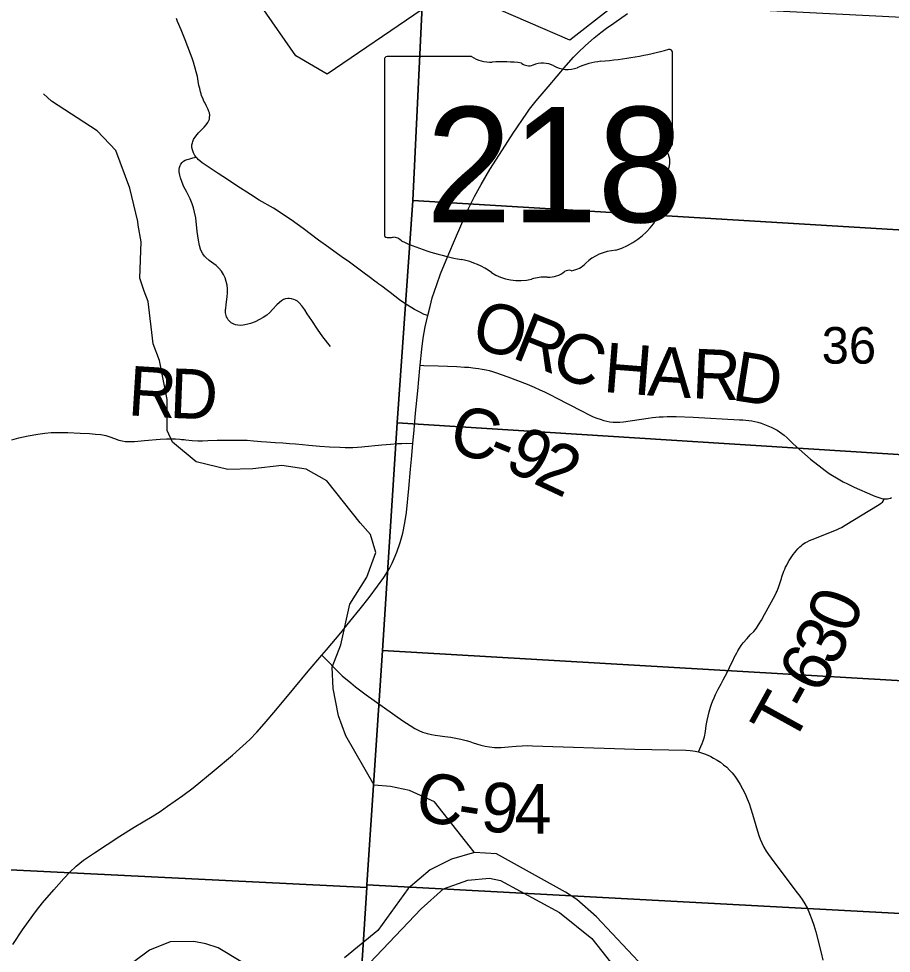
# Model space of a CAD drawing. Extents: x 21.4 to 65.3, y 4 to 26.
# Drawn here: x 25.873 to 26.871, y 19.331 to 20.4 of the extents above; entities that cross this region are included whole.
import ezdxf

# ---------------------------------------------------------------- set-up
doc = ezdxf.new("R2010")
doc.units = 0
for name, color, linetype in [('GM_X_County_Road', 7, 'Continuous'), ('GM_X_County_Road_Text', 7, 'Continuous'), ('GM_X_Major_River', 7, 'Continuous'), ('GM_X_Minor_River', 7, 'Continuous'), ('GM_X_Section', 7, 'Continuous'), ('GM_X_Section_Text', 7, 'Continuous'), ('GM_X_State_Location', 7, 'Continuous'), ('GM_X_State_Route', 7, 'Continuous'), ('GM_X_State_Shield', 7, 'Continuous'), ('GM_X_Township_Road', 7, 'Continuous'), ('GM_X_Township_Road_Text', 7, 'Continuous')]:
    doc.layers.add(name, color=color, linetype=linetype)

msp = doc.modelspace()

# ---------------------------------------------------------------- linework, layer by layer
at = {"layer": 'GM_X_County_Road'}
for points in [[(26.2896, 20.0931), (26.288, 20.0943), (26.2847, 20.0967), (26.2828, 20.0982), (26.28, 20.1003), (26.2751, 20.1041), (26.2662, 20.1106), (26.2586, 20.1162), (26.251, 20.1217), (26.2417, 20.1284), (26.2275, 20.1385), (26.2158, 20.1472), (26.1982, 20.1603), (26.1845, 20.1703), (26.1643, 20.1835), (26.1476, 20.193), (26.138, 20.1992), (26.1221, 20.2094), (26.1117, 20.2163), (26.1007, 20.2234), (26.0893, 20.2309), (26.0825, 20.2356), (26.0781, 20.2392), (26.0767, 20.2407), (26.0756, 20.242), (26.0743, 20.2438), (26.0734, 20.2453), (26.0725, 20.2469), (26.0713, 20.2503), (26.0707, 20.2532), (26.0708, 20.2562), (26.0713, 20.2584), (26.0718, 20.26), (26.0726, 20.2622), (26.0741, 20.2647), (26.0768, 20.268), (26.0785, 20.2697), (26.085, 20.2763), (26.0872, 20.2789), (26.089, 20.2815), (26.0903, 20.2838), (26.0905, 20.2847), (26.0908, 20.2856), (26.0911, 20.2873), (26.0912, 20.2901), (26.0908, 20.2926), (26.0903, 20.2943), (26.0893, 20.2966), (26.0872, 20.3011), (26.0855, 20.3044), (26.0846, 20.306), (26.0835, 20.3082), (26.0817, 20.3127), (26.0812, 20.3145), (26.0806, 20.3168), (26.0797, 20.3204), (26.0788, 20.3239), (26.0778, 20.3288), (26.077, 20.3342), (26.0756, 20.3395), (26.0725, 20.3506), (26.0709, 20.3553), (26.0691, 20.3604), (26.0632, 20.3761), (26.0585, 20.3876), (26.0544, 20.3973), (26.053, 20.4005)], [(26.3407, 20.0607), (26.3366, 20.0622), (26.3315, 20.0645), (26.3256, 20.0676), (26.3145, 20.0747), (26.3085, 20.0789), (26.3029, 20.0831), (26.2978, 20.0871), (26.2929, 20.0907), (26.2896, 20.0931)], [(26.3319, 20.0039), (26.3363, 20.0038), (26.3527, 20.0033), (26.3739, 20.0024), (26.3827, 20.0019), (26.3875, 20.0016), (26.3922, 20.0011), (26.3955, 20.0007), (26.3989, 20.0002), (26.4031, 19.9995), (26.4075, 19.9986), (26.4109, 19.9978), (26.4147, 19.9967), (26.4193, 19.9953), (26.4247, 19.9934), (26.4322, 19.9907), (26.4543, 19.9822), (26.4624, 19.9787), (26.469, 19.9758), (26.4741, 19.9734), (26.4782, 19.9715), (26.4826, 19.9693), (26.4867, 19.9672), (26.5175, 19.9513), (26.5247, 19.9476), (26.5301, 19.9451), (26.5341, 19.9435), (26.5379, 19.9422), (26.5423, 19.9408), (26.5457, 19.94), (26.5491, 19.9393), (26.5527, 19.9389), (26.5566, 19.9388), (26.5604, 19.9389), (26.5648, 19.9393), (26.593, 19.9433), (26.598, 19.944), (26.6018, 19.9445), (26.6056, 19.9448), (26.6101, 19.9451), (26.6148, 19.9453), (26.6196, 19.9452), (26.625, 19.9452), (26.6444, 19.9445), (26.6974, 19.9416), (26.7011, 19.9414), (26.7045, 19.9411), (26.708, 19.9408), (26.7114, 19.9403), (26.7149, 19.9395), (26.7184, 19.9387), (26.7221, 19.9376), (26.7261, 19.9361), (26.7298, 19.9346), (26.7338, 19.933), (26.7374, 19.9313), (26.7406, 19.9295), (26.7431, 19.9279), (26.7458, 19.926), (26.7487, 19.9238), (26.7518, 19.921), (26.7587, 19.9141), (26.772, 19.9023), (26.7788, 19.8966), (26.7922, 19.8862), (26.7956, 19.8836), (26.8002, 19.8803), (26.8123, 19.8728), (26.8162, 19.8706), (26.821, 19.8682), (26.8249, 19.8663), (26.8288, 19.8646), (26.8498, 19.8553), (26.8522, 19.8543), (26.8547, 19.8534), (26.8569, 19.8526), (26.8592, 19.8518), (26.8603, 19.8515), (26.8613, 19.8513), (26.8622, 19.8511), (26.8631, 19.851), (26.8651, 19.851), (26.8669, 19.8511), (26.8685, 19.8514), (26.8701, 19.852), (26.8713, 19.8528)], [(26.2196, 19.6722), (26.2218, 19.67), (26.2392, 19.6521), (26.2428, 19.6488), (26.2451, 19.6468), (26.2483, 19.644), (26.2526, 19.6405), (26.2581, 19.6361), (26.2703, 19.627), (26.3123, 19.5972), (26.3205, 19.5917), (26.3258, 19.5885), (26.3303, 19.5861), (26.3347, 19.5842), (26.3399, 19.5826), (26.3448, 19.5815), (26.3493, 19.5807), (26.3547, 19.58), (26.3604, 19.5793), (26.367, 19.5784), (26.3727, 19.5775), (26.3784, 19.5763), (26.3845, 19.5746), (26.3888, 19.5734), (26.3926, 19.5721), (26.3966, 19.5708), (26.4014, 19.5694), (26.4065, 19.5682), (26.4115, 19.5673), (26.4169, 19.5668), (26.4245, 19.5668), (26.4331, 19.5673), (26.4418, 19.5681), (26.4486, 19.5687), (26.4544, 19.5689), (26.4604, 19.5687), (26.5777, 19.5646), (26.6359, 19.5634), (26.641, 19.5632), (26.6441, 19.5629), (26.6468, 19.5625), (26.6506, 19.5616), (26.654, 19.5606), (26.6574, 19.5595), (26.6606, 19.5582), (26.6645, 19.5562), (26.6678, 19.5545), (26.6719, 19.5521), (26.6755, 19.5497), (26.6793, 19.5469), (26.6829, 19.544), (26.6861, 19.5409), (26.6891, 19.5375), (26.6919, 19.5339), (26.695, 19.5292), (26.6981, 19.5242), (26.7008, 19.5193), (26.7038, 19.5135), (26.7063, 19.508), (26.7086, 19.5024), (26.7105, 19.4966), (26.7124, 19.4904), (26.718, 19.4708), (26.7196, 19.4661), (26.7212, 19.4618), (26.723, 19.4576), (26.7254, 19.4528), (26.7281, 19.4482), (26.7307, 19.4442), (26.7368, 19.4357), (26.7633, 19.4005), (26.7663, 19.3965), (26.7691, 19.3927), (26.7722, 19.3878), (26.7747, 19.3832), (26.7777, 19.3766), (26.7803, 19.3698), (26.7826, 19.3633), (26.7848, 19.3557), (26.7909, 19.3317), (26.7927, 19.3232)]]:
    msp.add_lwpolyline(points, dxfattribs=at)
at = {"layer": 'GM_X_Major_River'}
for points in [[(26.5876, 19.3156), (26.5336, 19.373), (26.5112, 19.3929), (26.4983, 19.4012), (26.4194, 19.4451), (26.394, 19.4465), (26.368, 19.4387), (26.3435, 19.4268), (26.3182, 19.4055), (26.2837, 19.3574), (26.2453, 19.3261)], [(26.2447, 19.2889), (26.3331, 19.382), (26.3587, 19.4049), (26.3866, 19.415), (26.4112, 19.417), (26.4241, 19.4144), (26.4916, 19.378), (26.5284, 19.3483), (26.5997, 19.2576)], [(26.1269, 19.322), (26.1008, 19.3374), (26.0867, 19.3422), (26.0731, 19.3448), (26.0459, 19.3443), (26.0221, 19.3347), (25.9848, 19.3071)]]:
    msp.add_lwpolyline(points, dxfattribs=at)
at = {"layer": 'GM_X_Minor_River'}
for points in [[(26.7623, 20.4851), (26.6894, 20.4499), (26.5859, 20.4406), (26.5033, 20.3757), (26.4078, 20.417), (26.3342, 20.411), (26.2255, 20.3368), (26.1899, 20.3578), (26.1505, 20.4143)], [(26.2252, 19.8717), (26.2017, 19.885), (26.1737, 19.8891), (26.1407, 19.8853), (26.1119, 19.8845), (26.0755, 19.8936), (26.0486, 19.916), (26.0425, 19.9293), (26.0425, 19.9647), (26.0338, 20.0095), (26.0263, 20.0285), (26.0206, 20.0768), (26.0161, 20.0886), (26.0111, 20.1034), (26.0127, 20.1452), (26.0093, 20.1642), (26.0089, 20.1684), (25.9998, 20.2064), (25.9839, 20.2498), (25.9623, 20.2722), (25.91, 20.306), (25.9009, 20.3143)], [(26.3937, 19.4469), (26.3484, 19.5045), (26.3197, 19.5176), (26.2979, 19.5221), (26.2794, 19.5234), (26.2471, 19.5799), (26.2387, 19.603), (26.2325, 19.6343), (26.2314, 19.6586), (26.2412, 19.6841), (26.2517, 19.7305), (26.2708, 19.7614), (26.2811, 19.7896), (26.2753, 19.8103), (26.2632, 19.8236), (26.2251, 19.8717)]]:
    msp.add_lwpolyline(points, dxfattribs=at)
at = {"layer": 'GM_X_Section'}
for points in [[(25.2871, 20.4832), (26.3352, 20.4317), (26.3235, 20.1926), (26.3057, 19.938), (26.289, 19.6776), (26.2711, 19.4096), (26.2708, 19.4063), (25.208, 19.459)], [(26.3352, 20.4317), (26.6191, 20.4157), (27.367, 20.3777), (27.3527, 20.1302), (26.3235, 20.1926)], [(27.3527, 20.1302), (27.3378, 19.8728), (26.3057, 19.938), (26.3235, 20.1926)], [(26.3057, 19.938), (27.3378, 19.8728), (27.3231, 19.6175), (26.289, 19.6776)], [(27.3231, 19.6175), (27.3079, 19.3538), (26.2711, 19.4096), (26.289, 19.6776)], [(25.208, 19.459), (26.2708, 19.4063), (26.2556, 19.168), (26.2403, 18.9172), (26.2238, 18.6579), (26.208, 18.4108), (25.1472, 18.4529)], [(26.2711, 19.4096), (27.3079, 19.3538), (27.2925, 19.1065), (26.2556, 19.168), (26.2708, 19.4063)]]:
    msp.add_lwpolyline(points, close=True, dxfattribs=at)
at = {"layer": 'GM_X_State_Route'}
msp.add_lwpolyline([(25.866, 19.3414), (25.877, 19.358), (25.8889, 19.3746), (25.8931, 19.3803), (25.8999, 19.3888), (25.9128, 19.4039), (25.9243, 19.4168), (25.9311, 19.424), (25.9383, 19.4308), (25.9469, 19.4376), (25.9592, 19.446), (25.9883, 19.4652), (26.0046, 19.4754), (26.0254, 19.4878), (26.0344, 19.4934), (26.043, 19.4995), (26.0605, 19.5117), (26.0721, 19.5205), (26.0961, 19.5404), (26.1171, 19.558), (26.1371, 19.5758), (26.1449, 19.584), (26.1535, 19.5937), (26.1668, 19.6094), (26.1875, 19.6342), (26.2039, 19.6538), (26.2196, 19.6722), (26.2248, 19.6783), (26.2411, 19.6977), (26.2515, 19.7107), (26.2632, 19.7251), (26.2737, 19.7383), (26.2833, 19.7511), (26.2903, 19.761), (26.297, 19.7715), (26.3, 19.7774), (26.3023, 19.7827), (26.3053, 19.7902), (26.309, 19.801), (26.3122, 19.8117), (26.3145, 19.8235), (26.3162, 19.8355), (26.3191, 19.8631), (26.3209, 19.885), (26.322, 19.8964), (26.3235, 19.9144), (26.3251, 19.9302), (26.3267, 19.9492), (26.3292, 19.9747), (26.3315, 20.0005), (26.3319, 20.0039), (26.3339, 20.0225), (26.3356, 20.0348), (26.3379, 20.0478), (26.3407, 20.0607), (26.3433, 20.0711), (26.3459, 20.0811), (26.3509, 20.0964), (26.3552, 20.1084), (26.3616, 20.1243), (26.37, 20.1439), (26.3807, 20.1689), (26.3873, 20.1833), (26.394, 20.1971), (26.4017, 20.2108), (26.4118, 20.228), (26.4262, 20.2503), (26.4386, 20.2696), (26.4539, 20.2922), (26.4572, 20.2968), (26.4649, 20.3066), (26.4783, 20.3226), (26.4992, 20.3469), (26.5076, 20.3563), (26.5127, 20.3616), (26.5212, 20.3697), (26.5313, 20.3785), (26.5388, 20.3846), (26.5453, 20.3895), (26.5537, 20.3954), (26.5694, 20.4062)], dxfattribs=at)
at = {"layer": 'GM_X_State_Shield'}
for p, q in [((26.6206, 20.2573), (26.6206, 20.362)), ((26.2911, 20.3536), (26.2911, 20.1535)), ((26.3908, 20.3571), (26.2943, 20.3571)), ((26.6206, 20.2574), (26.6206, 20.2573))]:
    msp.add_line(p, q, dxfattribs=at)
for centre, major_axis, start_param, end_param in [((26.5032, 20.6299), (0.3495, 0), 4.814394, 5.042369), ((26.617, 20.3624), (0.00367, 0), 6.141152, 7.989035), ((26.2948, 20.354), (0.00382, 0), 1.712693, 3.28349), ((26.4138, 20.3803), (0.037, 0), 4.042523, 4.731795), ((26.4261, 20.2447), (0.133, 0), 1.404758, 1.657858), ((26.4563, 20.3551), (0.0107, 0), 3.836095, 5.185415), ((26.472, 20.3319), (0.0222, 0), 0.950623, 2.079405), ((26.5478, 20.2959), (0.0703, 0), 1.699011, 2.107814), ((26.5006, 20.3637), (0.0267, 0), 4.081561, 5.145723), ((26.6198, 20.2496), (0.00568, 0), 1.883978, 3.671073), ((26.6167, 20.2569), (0.00393, 0), 5.05454, 6.418171), ((26.5837, 20.2364), (0.0341, 0), 5.934695, 6.695948), ((26.6338, 20.2135), (0.0248, 0), 2.387724, 3.262537), ((26.5228, 20.2002), (0.0874, 0), 5.101752, 6.440018), ((26.2949, 20.1531), (0.00385, 0), 3.00124, 4.508301), ((26.2955, 20.1735), (0.0294, 0), 4.665946, 4.897461), ((26.3015, 20.1419), (0.0106, 0), 0.519207, 1.627899), ((26.4353, 20.3217), (0.2524, 0), 4.195997, 4.488961), ((26.5597, 20.0973), (0.0479, 0), 1.647645, 2.488434), ((26.36, 20.0636), (0.079, 0), 0.823519, 1.323587), ((26.5022, 20.1066), (0.00752, 0), 1.147584, 2.315152), ((26.499, 20.1341), (0.0282, 0), 4.937069, 5.64225), ((26.4455, 20.141), (0.0501, 0), 4.026481, 4.996735), ((26.4744, 20.0718), (0.0412, 0), 1.495662, 1.94098), ((26.4781, 20.126), (0.0267, 0), 4.691044, 5.507374)]:
    msp.add_ellipse(centre, major_axis=major_axis, ratio=0.8, start_param=start_param, end_param=end_param, dxfattribs=at)
at = {"layer": 'GM_X_Township_Road'}
for points in [[(26.2295, 20.0254), (26.2207, 20.0366), (26.2145, 20.0453), (26.208, 20.055), (26.2028, 20.0627), (26.1999, 20.0674), (26.1965, 20.0719), (26.1937, 20.0752), (26.1915, 20.0772), (26.1895, 20.0785), (26.1875, 20.0793), (26.1849, 20.08), (26.1822, 20.0803), (26.1804, 20.0803), (26.1779, 20.0799), (26.1756, 20.079), (26.1735, 20.0778), (26.171, 20.0759), (26.1678, 20.073), (26.1632, 20.0679), (26.1599, 20.0642), (26.1566, 20.0614), (26.1525, 20.0586), (26.1481, 20.0562), (26.1431, 20.0538), (26.1379, 20.0518), (26.1331, 20.0504), (26.1294, 20.0497), (26.1263, 20.0495), (26.1232, 20.0497), (26.1208, 20.0502), (26.1179, 20.0513), (26.1158, 20.0526), (26.1139, 20.0542), (26.1123, 20.056), (26.111, 20.0582), (26.1104, 20.0594), (26.1099, 20.0607), (26.1095, 20.0625), (26.1093, 20.064), (26.1092, 20.0658), (26.1094, 20.0677), (26.1095, 20.069), (26.11, 20.0733), (26.1112, 20.0823), (26.1115, 20.0869), (26.1115, 20.0912), (26.111, 20.0955), (26.1101, 20.0998), (26.1087, 20.1039), (26.1068, 20.1078), (26.1045, 20.1115), (26.1017, 20.1149), (26.0986, 20.1179), (26.0907, 20.1239), (26.0869, 20.1271), (26.0852, 20.1289), (26.0833, 20.1314), (26.0818, 20.1341), (26.0806, 20.1369), (26.0795, 20.1411), (26.0782, 20.1472), (26.0769, 20.157), (26.0751, 20.1725), (26.0739, 20.1792), (26.0727, 20.184), (26.0711, 20.1887), (26.0687, 20.1944), (26.0645, 20.2026), (26.0617, 20.2081), (26.0595, 20.2132), (26.0578, 20.2185), (26.057, 20.2215), (26.0564, 20.2252), (26.0564, 20.2283), (26.0567, 20.2301), (26.0574, 20.2325), (26.0582, 20.2341), (26.0597, 20.2361), (26.0611, 20.2374), (26.0631, 20.2386), (26.0652, 20.2393), (26.0683, 20.2402), (26.0719, 20.2411), (26.0756, 20.242)], [(25.8647, 19.9187), (25.8728, 19.921), (25.8833, 19.9232), (25.8945, 19.9251), (25.9024, 19.9263), (25.9097, 19.927), (25.9171, 19.9272), (25.9221, 19.927), (25.9288, 19.9269), (25.943, 19.9263), (25.9536, 19.9258), (25.9605, 19.9253), (25.9666, 19.9246), (25.9721, 19.9234), (25.9768, 19.922), (25.9821, 19.9201), (25.9873, 19.9184), (25.9908, 19.9175), (25.9944, 19.9169), (25.9992, 19.9166), (26.0052, 19.9168), (26.0165, 19.9179), (26.0345, 19.9195), (26.0418, 19.9199), (26.046, 19.9199), (26.0522, 19.9197), (26.0571, 19.9194), (26.0589, 19.9192), (26.062, 19.9189), (26.0639, 19.9187), (26.0712, 19.9179), (26.0774, 19.9174), (26.0799, 19.9174), (26.0829, 19.9173), (26.089, 19.9177), (26.0997, 19.9181), (26.1062, 19.9184), (26.1159, 19.9184), (26.1236, 19.9184), (26.1291, 19.9184), (26.1342, 19.9181), (26.1414, 19.9175), (26.1457, 19.9171), (26.15, 19.9169), (26.1561, 19.9164), (26.166, 19.9157), (26.1747, 19.9152), (26.1824, 19.9146), (26.1893, 19.914), (26.1973, 19.9132), (26.2047, 19.9125), (26.217, 19.9113), (26.2282, 19.9105), (26.24, 19.9101), (26.2462, 19.91), (26.2548, 19.9099), (26.2603, 19.9101), (26.2651, 19.9105), (26.2686, 19.9109), (26.2728, 19.9113), (26.2801, 19.912), (26.2844, 19.9124), (26.2881, 19.9128), (26.298, 19.9137), (26.306, 19.9143), (26.3112, 19.9145), (26.3163, 19.9147), (26.3235, 19.9144)], [(26.6506, 19.5616), (26.6548, 19.5714), (26.6559, 19.5742), (26.6567, 19.5765), (26.6575, 19.5788), (26.6579, 19.5808), (26.6583, 19.5829), (26.6585, 19.5849), (26.6593, 19.5918), (26.6596, 19.5936), (26.6599, 19.5955), (26.6603, 19.5976), (26.6627, 19.6076), (26.6634, 19.6102), (26.6642, 19.6126), (26.6655, 19.6162), (26.6667, 19.6194), (26.6684, 19.6233), (26.6701, 19.6272), (26.6731, 19.6333), (26.6763, 19.6393), (26.6787, 19.6439), (26.6812, 19.6484), (26.6836, 19.6532), (26.6861, 19.6583), (26.6884, 19.6632), (26.6901, 19.6667), (26.6914, 19.6697), (26.6928, 19.6724), (26.6942, 19.675), (26.6956, 19.6774), (26.6973, 19.6803), (26.6993, 19.6832), (26.7017, 19.6863), (26.7061, 19.6914), (26.7097, 19.6954), (26.7137, 19.6994), (26.7167, 19.7031), (26.7193, 19.7068), (26.7226, 19.7122), (26.7262, 19.7187), (26.7383, 19.741), (26.7395, 19.7434), (26.7405, 19.7455), (26.7413, 19.7476), (26.742, 19.7497), (26.7453, 19.7601), (26.7459, 19.762), (26.7466, 19.7641), (26.7474, 19.7662), (26.7482, 19.7684), (26.7492, 19.7707), (26.7502, 19.7729), (26.7514, 19.7753), (26.7529, 19.7781), (26.7542, 19.7804), (26.7557, 19.7828), (26.7573, 19.7853), (26.759, 19.7875), (26.7606, 19.7896), (26.7622, 19.7915), (26.7642, 19.7938), (26.7665, 19.7962), (26.7679, 19.7975), (26.7695, 19.7987), (26.7712, 19.7999), (26.773, 19.801), (26.775, 19.8021), (26.7775, 19.8033), (26.7806, 19.8046), (26.8085, 19.8158), (26.8114, 19.8171), (26.814, 19.8185), (26.8184, 19.8211), (26.8465, 19.8382), (26.8572, 19.8447), (26.8588, 19.8456), (26.86, 19.8466), (26.8609, 19.8475), (26.8617, 19.8486), (26.8631, 19.851)]]:
    msp.add_lwpolyline(points, dxfattribs=at)

# ---------------------------------------------------------------- texts
at = {"layer": 'GM_X_County_Road_Text'}
for s, rotation, p in [('O', 346.1466, (26.3888, 20.0245)), ('R', 338.1479, (26.4354, 20.0132)), ('C', 337.5053, (26.4785, 19.9959)), ('H', 355.5342, (26.5406, 19.9735)), ('A', 356.3425, (26.5913, 19.9695)), ('R', 357.5012, (26.6424, 19.9663)), ('D', 351.0036, (26.6874, 19.9644)), ('C', 346.7769, (26.3629, 19.9048)), ('9', 332.8252, (26.4266, 19.8866)), ('-', 337.9181, (26.4062, 19.8948)), ('2', 334.851, (26.4597, 19.8696)), ('C', 348.1983, (26.3237, 19.4855)), ('9', 355.2721, (26.4, 19.4712)), ('4', 0.07, (26.4401, 19.4681)), ('-', 351.097, (26.3725, 19.4754))]:
    msp.add_text(s, height=0.0568, rotation=rotation, dxfattribs=at).set_placement(p)
at = {"layer": 'GM_X_Section_Text'}
msp.add_text('36', height=0.04186, rotation=0, dxfattribs=at).set_placement((26.7915, 20.0058))
at = {"layer": 'GM_X_State_Location'}
for s, p in [('s', (26.4522, 20.2402)), ('r', (26.4521, 20.2402))]:
    msp.add_text(s, height=0.000189, dxfattribs=at).set_placement(p)
msp.add_text('218', height=0.000189, rotation=0, dxfattribs=at).set_placement((26.3853, 20.2265))
at = {"layer": 'GM_X_State_Shield'}
msp.add_text('218', height=0.13184, dxfattribs=at).set_placement((26.3387, 20.1676))
at = {"layer": 'GM_X_Township_Road_Text'}
for s, rotation, p in [('R', 356.4285, (25.9967, 19.9468)), ('D', 357.7398, (26.0447, 19.9438)), ('0', 68.8146, (26.8255, 19.6948)), ('3', 62.6549, (26.8067, 19.6576)), ('6', 61.4427, (26.7894, 19.6257)), ('T', 61.1593, (26.7575, 19.5678)), ('-', 61.2133, (26.778, 19.605))]:
    msp.add_text(s, height=0.0568, rotation=rotation, dxfattribs=at).set_placement(p)

doc.saveas('drawing.dxf')
